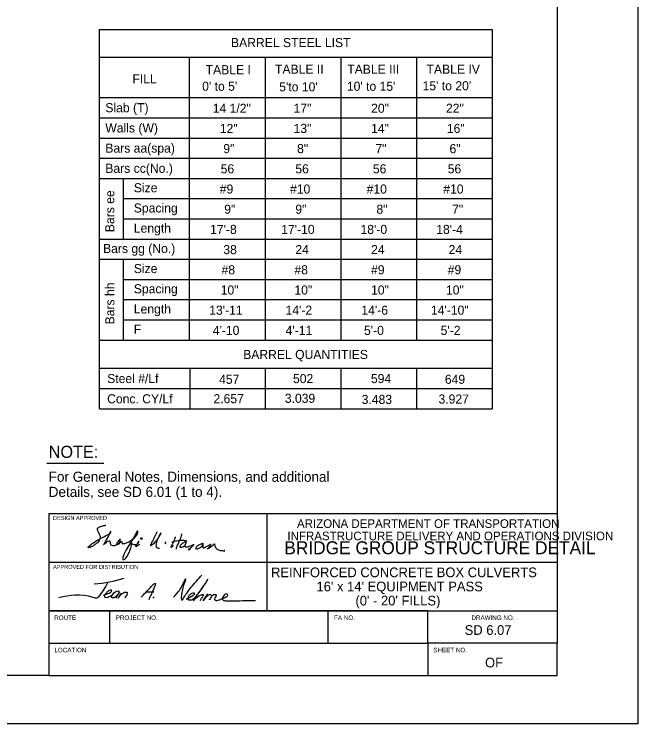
# Model space of a CAD drawing. Extents: x -0.08 to 2.83, y -0.03 to 1.92.
# Drawn here: x 2.029 to 2.833, y 0 to 0.915 of the extents above; entities that cross this region are included whole.
import ezdxf

# ---------------------------------------------------------------- set-up
doc = ezdxf.new("R2010")
doc.units = 0
for name, color, linetype in [('49', 7, 'Continuous'), ('55', 7, 'Continuous'), ('57', 7, 'Continuous'), ('62', 7, 'Continuous'), ('63', 7, 'Continuous')]:
    doc.layers.add(name, color=color, linetype=linetype)

msp = doc.modelspace()

# ---------------------------------------------------------------- linework, layer by layer
at = {"layer": '49'}
msp.add_line((2.13966, 0.49488), (2.13966, 0.49456), dxfattribs=at)
at = {"layer": '55'}
for p, q in [((2.13899, 0.89521), (2.13899, 0.40618)), ((2.13899, 0.89521), (2.64541, 0.89521)), ((2.64563, 0.89521), (2.64563, 0.40618)), ((2.13854, 0.85931), (2.64563, 0.85931)), ((2.2551, 0.85931), (2.2551, 0.49473)), ((2.35275, 0.85931), (2.35275, 0.49473)), ((2.45041, 0.85931), (2.45041, 0.49473)), ((2.54806, 0.85931), (2.54806, 0.49473)), ((2.13921, 0.80723), (2.64563, 0.80723)), ((2.13921, 0.78118), (2.64563, 0.78118)), ((2.13921, 0.75514), (2.64563, 0.75514)), ((2.13921, 0.7291), (2.64563, 0.7291)), ((2.13899, 0.70306), (2.64563, 0.70306)), ((2.17046, 0.62493), (2.17046, 0.70306)), ((2.17046, 0.67702), (2.64563, 0.67702)), ((2.17046, 0.65098), (2.64563, 0.65098)), ((2.13899, 0.62493), (2.64563, 0.62493)), ((2.13899, 0.59889), (2.64563, 0.59889)), ((2.17046, 0.49473), (2.17046, 0.59889)), ((2.17046, 0.57285), (2.64563, 0.57285)), ((2.17046, 0.54681), (2.64563, 0.54681)), ((2.17046, 0.52077), (2.64563, 0.52077)), ((2.13899, 0.49473), (2.64541, 0.49473)), ((2.13921, 0.45827), (2.64563, 0.45827)), ((2.25577, 0.45827), (2.25577, 0.40618)), ((2.35275, 0.45827), (2.35275, 0.40618)), ((2.45041, 0.45827), (2.45041, 0.40618)), ((2.54806, 0.45827), (2.54806, 0.40618)), ((2.13921, 0.43223), (2.64541, 0.43223)), ((2.13921, 0.40618), (2.64541, 0.40618))]:
    msp.add_line(p, q, dxfattribs=at)
at = {"layer": '57'}
for p, q in [((2.64631, 0.49473), (2.64631, 0.49456)), ((2.07131, 0.33607), (2.14477, 0.33607))]:
    msp.add_line(p, q, dxfattribs=at)
for points in [[(2.14765, 0.25562), (2.14682, 0.25571), (2.14575, 0.25542), (2.14487, 0.25532), (2.14397, 0.25503), (2.14311, 0.25475), (2.14203, 0.25429), (2.14043, 0.25389), (2.13901, 0.25331), (2.13813, 0.25284), (2.13758, 0.25263), (2.13706, 0.2524), (2.13655, 0.25191), (2.13637, 0.25143), (2.13634, 0.25038), (2.13646, 0.24988), (2.13669, 0.24909), (2.13707, 0.24825), (2.13754, 0.24729), (2.13802, 0.24626), (2.13848, 0.24568), (2.1391, 0.24444), (2.13948, 0.24359), (2.13985, 0.24285), (2.14011, 0.24143), (2.14019, 0.24048), (2.14006, 0.2395), (2.13967, 0.23801), (2.13887, 0.23634), (2.13823, 0.23519), (2.13663, 0.23333), (2.13514, 0.23225), (2.13328, 0.23066), (2.13172, 0.22974), (2.13035, 0.22879), (2.12878, 0.22803), (2.12732, 0.22727), (2.12575, 0.22684), (2.12502, 0.22692), (2.12462, 0.22757), (2.12482, 0.22803), (2.12536, 0.22854), (2.12583, 0.22911), (2.12687, 0.23003), (2.12901, 0.23148), (2.12993, 0.23223), (2.13153, 0.23337), (2.13326, 0.23448), (2.13516, 0.23574), (2.13681, 0.23665), (2.14133, 0.23946), (2.14564, 0.24158), (2.14763, 0.24265), (2.14977, 0.24371), (2.15138, 0.24446), (2.15266, 0.24523), (2.15357, 0.24588), (2.15395, 0.24653), (2.15403, 0.24774), (2.15357, 0.24792), (2.15339, 0.24772), (2.15326, 0.24744), (2.15189, 0.24408), (2.15104, 0.24225), (2.14793, 0.2371), (2.14615, 0.23392), (2.14537, 0.23259), (2.14456, 0.23092), (2.14471, 0.23073), (2.14621, 0.23237), (2.14786, 0.23379), (2.14933, 0.2349), (2.15041, 0.23553), (2.15025, 0.23554), (2.15166, 0.23596), (2.15233, 0.23575), (2.15248, 0.23551), (2.15292, 0.23413), (2.15298, 0.23275), (2.15347, 0.23157), (2.15416, 0.23064), (2.15662, 0.23007), (2.15903, 0.23008), (2.16063, 0.23083), (2.16326, 0.23175), (2.16493, 0.23298), (2.16588, 0.2341), (2.1662, 0.23616), (2.16645, 0.23743), (2.16619, 0.23773), (2.16568, 0.23744), (2.16444, 0.2361), (2.16299, 0.23465), (2.16243, 0.234), (2.16167, 0.23323), (2.16131, 0.23193), (2.16152, 0.23111), (2.16315, 0.23186), (2.16495, 0.23312), (2.16659, 0.23422), (2.1675, 0.23485)], [(2.1675, 0.23485), (2.16768, 0.23502), (2.16803, 0.23499), (2.16833, 0.23428), (2.16809, 0.23323), (2.1685, 0.23253), (2.16938, 0.23231), (2.17073, 0.23226), (2.17219, 0.23262), (2.17432, 0.23335), (2.17707, 0.2347), (2.17923, 0.23592), (2.18111, 0.23698), (2.18401, 0.23935), (2.18673, 0.24251), (2.1874, 0.24345), (2.18795, 0.24413), (2.18885, 0.24684), (2.18861, 0.24817), (2.18803, 0.24838), (2.18525, 0.24365), (2.18363, 0.24013), (2.17856, 0.23217), (2.17642, 0.22845), (2.17367, 0.22436), (2.17077, 0.21821), (2.16978, 0.21578), (2.16922, 0.21263), (2.16931, 0.21192), (2.17007, 0.21144), (2.17188, 0.21228), (2.17301, 0.21331), (2.17493, 0.21608), (2.17752, 0.22087), (2.17895, 0.22416), (2.17971, 0.22647), (2.18065, 0.22981), (2.18078, 0.23184), (2.18067, 0.23323), (2.18006, 0.23363), (2.17971, 0.23383), (2.17996, 0.23312), (2.18067, 0.23272), (2.18133, 0.23216), (2.18235, 0.23173), (2.18352, 0.2313), (2.18407, 0.23126), (2.18577, 0.23115), (2.18651, 0.23125), (2.18788, 0.23169), (2.18906, 0.23271), (2.18935, 0.23298), (2.19013, 0.23462), (2.19023, 0.23513), (2.18976, 0.23544), (2.18843, 0.23244), (2.1867, 0.2305), (2.18629, 0.22968), (2.18597, 0.22898), (2.18621, 0.22854), (2.18855, 0.23002), (2.18946, 0.2305), (2.19059, 0.23118), (2.19141, 0.23178)], [(2.21321, 0.24728), (2.21278, 0.24633), (2.21192, 0.2446), (2.21109, 0.24289), (2.20987, 0.24003), (2.20924, 0.23883), (2.20839, 0.23714), (2.20749, 0.23532), (2.20656, 0.23362), (2.20585, 0.23209), (2.20522, 0.23093), (2.20498, 0.23028), (2.20498, 0.22995), (2.20514, 0.22994), (2.20538, 0.22984), (2.20569, 0.22998), (2.20645, 0.23048), (2.20741, 0.23118), (2.20881, 0.23228), (2.21007, 0.23343), (2.2113, 0.23468), (2.21223, 0.23566), (2.21333, 0.23669), (2.21398, 0.23754), (2.2148, 0.23898), (2.21596, 0.24094), (2.21666, 0.24203), (2.21782, 0.24413), (2.21837, 0.24483), (2.21887, 0.24558), (2.21893, 0.24581), (2.21882, 0.24594), (2.21866, 0.246), (2.21854, 0.24593), (2.21806, 0.24521), (2.21715, 0.24405), (2.21599, 0.24204), (2.21572, 0.24131), (2.21528, 0.24042), (2.21488, 0.23963), (2.21393, 0.23749), (2.21329, 0.23598), (2.21302, 0.23478), (2.21269, 0.23374), (2.21253, 0.23244), (2.21229, 0.23068), (2.21218, 0.22945), (2.21231, 0.22828), (2.21257, 0.22781), (2.21318, 0.22732), (2.21379, 0.22691), (2.21433, 0.22667), (2.21497, 0.22648), (2.21556, 0.2264), (2.21619, 0.22636), (2.21665, 0.22637)], [(2.19468, 0.23875), (2.1943, 0.23878), (2.19381, 0.23888), (2.19338, 0.23913), (2.19307, 0.23928), (2.19284, 0.23933), (2.19253, 0.23933), (2.19238, 0.23916), (2.1922, 0.23895), (2.19217, 0.23886), (2.19224, 0.23861), (2.19245, 0.23854), (2.19273, 0.23851), (2.19302, 0.23849), (2.1935, 0.23855), (2.19382, 0.23856), (2.19419, 0.23856), (2.19455, 0.23867), (2.19471, 0.23872)], [(2.23711, 0.24121), (2.23674, 0.24001), (2.23642, 0.239), (2.23579, 0.23723), (2.23502, 0.23525), (2.23462, 0.2345), (2.23406, 0.23333), (2.23329, 0.23174), (2.23267, 0.23059), (2.23222, 0.22966), (2.23172, 0.22875), (2.2315, 0.22823), (2.23146, 0.2278), (2.23159, 0.22758), (2.23184, 0.22757), (2.232, 0.22763), (2.23258, 0.22801), (2.23313, 0.22838), (2.23337, 0.22858), (2.23364, 0.22878), (2.23378, 0.22887), (2.23399, 0.22905), (2.23421, 0.22928), (2.23441, 0.22947), (2.23448, 0.22961), (2.23467, 0.22983)], [(2.24473, 0.24483), (2.24497, 0.24428), (2.24498, 0.24372), (2.24493, 0.24321), (2.24468, 0.24225), (2.24431, 0.24076), (2.24388, 0.23971), (2.24318, 0.23801), (2.24267, 0.23695), (2.24213, 0.23588), (2.24099, 0.23343), (2.24057, 0.23259), (2.23951, 0.23037), (2.23933, 0.22998), (2.23898, 0.22908), (2.23857, 0.22768), (2.23835, 0.22672), (2.23821, 0.22563), (2.23811, 0.22523)], [(2.22443, 0.23244), (2.22472, 0.23308), (2.2246, 0.23376), (2.22436, 0.23406), (2.22408, 0.23412), (2.22398, 0.23393), (2.22388, 0.23324), (2.224, 0.23256), (2.22423, 0.23234), (2.22434, 0.2322), (2.22443, 0.23224), (2.2244, 0.23238)], [(2.23248, 0.23456), (2.23325, 0.23476), (2.2342, 0.23501), (2.23568, 0.23543), (2.23742, 0.23576), (2.23878, 0.23593), (2.24092, 0.23616), (2.24296, 0.23643), (2.24483, 0.23658), (2.24631, 0.23661), (2.24751, 0.23662), (2.24815, 0.23658), (2.24954, 0.23651), (2.25052, 0.23638), (2.25088, 0.23621), (2.25113, 0.23568), (2.2507, 0.2337), (2.25061, 0.23341), (2.25006, 0.23176), (2.24968, 0.23083), (2.24923, 0.2298), (2.24903, 0.22937), (2.24881, 0.22913), (2.24855, 0.22885), (2.24788, 0.22845), (2.24669, 0.22782), (2.24572, 0.22757), (2.24486, 0.22728), (2.24453, 0.22723), (2.24402, 0.22721), (2.24346, 0.22738), (2.24333, 0.22753), (2.24326, 0.22773), (2.24329, 0.22813), (2.24333, 0.22875), (2.24351, 0.22929), (2.24369, 0.22982), (2.24413, 0.23055), (2.24473, 0.23118), (2.24562, 0.23205), (2.24626, 0.23258), (2.24677, 0.23295), (2.24743, 0.23348), (2.24812, 0.23387), (2.24898, 0.23437), (2.24957, 0.23468), (2.25026, 0.23503), (2.25053, 0.23503), (2.25075, 0.23493), (2.25082, 0.23468), (2.25057, 0.23343), (2.25053, 0.23315), (2.25026, 0.23215), (2.24986, 0.23102), (2.2495, 0.23), (2.24939, 0.2295), (2.24935, 0.22926), (2.24932, 0.22911), (2.24933, 0.22867), (2.24944, 0.22839), (2.24977, 0.2281), (2.2499, 0.22803), (2.25012, 0.22803), (2.2505, 0.22796), (2.25113, 0.22796), (2.25153, 0.22798), (2.25188, 0.22807), (2.25251, 0.22818), (2.25313, 0.22828), (2.25369, 0.22836), (2.25436, 0.22853), (2.25515, 0.22883), (2.25633, 0.22935), (2.25781, 0.22992), (2.25893, 0.23036), (2.25968, 0.23067), (2.26019, 0.23098), (2.2608, 0.23112), (2.26094, 0.23098), (2.26057, 0.23036), (2.26004, 0.22976), (2.25931, 0.22903), (2.25887, 0.22862), (2.25828, 0.22803), (2.25718, 0.22698), (2.25408, 0.22424), (2.25384, 0.22398), (2.25413, 0.22412), (2.25504, 0.22455), (2.25579, 0.22489), (2.25632, 0.22513), (2.25663, 0.22528)], [(2.27233, 0.23026), (2.27212, 0.2318), (2.27153, 0.23226), (2.27104, 0.23214), (2.26923, 0.23137), (2.2681, 0.23077), (2.26717, 0.23022), (2.26638, 0.22968), (2.26546, 0.22897), (2.26466, 0.22842), (2.26423, 0.22782), (2.26369, 0.2272), (2.26337, 0.22659), (2.26336, 0.22625), (2.26337, 0.22586), (2.26366, 0.22562), (2.26398, 0.22548), (2.26441, 0.22542), (2.26464, 0.22542), (2.26516, 0.22547), (2.26554, 0.22556), (2.2664, 0.22583), (2.26779, 0.22633), (2.26861, 0.22685), (2.26952, 0.22746), (2.27029, 0.22808), (2.27109, 0.22873), (2.27183, 0.22942), (2.27243, 0.23006), (2.27312, 0.23148), (2.27319, 0.23218), (2.27303, 0.23268), (2.27271, 0.23234), (2.27258, 0.23171), (2.27262, 0.23101), (2.27263, 0.22988), (2.27258, 0.22914), (2.27257, 0.22827), (2.27259, 0.22769), (2.27259, 0.22686), (2.27266, 0.22673), (2.27281, 0.22671), (2.27373, 0.22695), (2.27465, 0.22718), (2.27539, 0.22753), (2.2761, 0.22788), (2.27641, 0.22803), (2.27723, 0.22842), (2.27798, 0.22885), (2.27917, 0.22956), (2.28043, 0.2302), (2.28166, 0.23094), (2.28213, 0.23122), (2.28297, 0.23177), (2.28313, 0.23174), (2.28293, 0.23104), (2.28261, 0.23033), (2.28215, 0.22959), (2.28155, 0.22873), (2.28111, 0.22811), (2.27994, 0.22684), (2.27862, 0.22555), (2.27853, 0.22532), (2.27868, 0.22528), (2.28006, 0.22628), (2.28188, 0.22757), (2.28343, 0.22858), (2.28454, 0.22938), (2.28567, 0.23033), (2.28698, 0.23175), (2.28705, 0.23179), (2.28728, 0.23206), (2.28742, 0.23198), (2.28766, 0.23069), (2.2879, 0.22988), (2.28822, 0.22903), (2.28848, 0.22836), (2.28878, 0.22766), (2.28907, 0.22713), (2.28958, 0.22627), (2.28999, 0.22582), (2.29046, 0.22545), (2.29094, 0.22511), (2.29132, 0.22488), (2.29228, 0.2244), (2.29317, 0.22411), (2.29438, 0.22369), (2.29511, 0.22358), (2.29611, 0.22335), (2.29699, 0.22325), (2.29795, 0.22323), (2.29877, 0.22316), (2.29951, 0.22312), (2.30051, 0.22297), (2.30093, 0.22293), (2.30071, 0.22307), (2.30038, 0.22326), (2.30007, 0.22348), (2.29987, 0.2236)]]:
    msp.add_lwpolyline(points, dxfattribs=at)
msp.add_arc((2.12576, 0.32651), 0.14607, 272.67102, 288.18495, dxfattribs=at)
msp.add_ellipse((2.1597, 0.16674), major_axis=(0.00445, 0.00414), ratio=0.425517, dxfattribs=at)
for points in [[(2.23468, 0.16329), (2.24247, 0.17206), (2.2468, 0.17993), (2.25055, 0.18688), (2.24978, 0.18448), (2.24873, 0.18168), (2.24786, 0.17853), (2.24593, 0.17117), (2.24575, 0.15925), (2.24768, 0.16223), (2.25383, 0.17108), (2.25913, 0.17799), (2.26284, 0.18217), (2.26953, 0.18973), (2.27125, 0.19154)], [(2.27913, 0.18645), (2.26691, 0.16866), (2.26002, 0.15884), (2.27102, 0.16638), (2.27174, 0.16649), (2.27323, 0.16633), (2.27308, 0.16531), (2.27148, 0.1627), (2.26896, 0.15855)], [(2.15026, 0.18245), (2.13747, 0.1632), (2.13658, 0.16231), (2.13123, 0.16275), (2.08684, 0.16261)], [(2.19315, 0.16345), (2.19896, 0.16933), (2.20501, 0.17574), (2.20724, 0.17819), (2.20941, 0.1803), (2.21138, 0.18096), (2.2113, 0.17937), (2.21077, 0.17794), (2.20906, 0.17363), (2.20497, 0.16464), (2.20276, 0.16)], [(2.25098, 0.16082), (2.25957, 0.16531), (2.26102, 0.16633), (2.26204, 0.16779), (2.26175, 0.16822), (2.26001, 0.16837), (2.25666, 0.16706), (2.25405, 0.16415), (2.25332, 0.16197), (2.25332, 0.16095), (2.25581, 0.15961), (2.26008, 0.16091), (2.26408, 0.1646), (2.27308, 0.1773)], [(2.14468, 0.16595), (2.15189, 0.16856), (2.15402, 0.16987), (2.155, 0.1715), (2.155, 0.17216), (2.15369, 0.17232), (2.15108, 0.1715), (2.1483, 0.16889), (2.1465, 0.16676), (2.14569, 0.16464), (2.14634, 0.16333), (2.14912, 0.16317), (2.15298, 0.16457), (2.15512, 0.16583), (2.15712, 0.16742), (2.15716, 0.16742)], [(2.16416, 0.17088), (2.16467, 0.1696), (2.16316, 0.16671), (2.16115, 0.16432), (2.16077, 0.16281), (2.16153, 0.16206)], [(2.16731, 0.16847), (2.16582, 0.16612), (2.16341, 0.16218), (2.16591, 0.16562), (2.16907, 0.16797), (2.17045, 0.16897), (2.17488, 0.16916), (2.17524, 0.16783), (2.17478, 0.16626), (2.17294, 0.16391), (2.17196, 0.1618)], [(2.20019, 0.17022), (2.20269, 0.17029), (2.20533, 0.17015), (2.20922, 0.17029)], [(2.27878, 0.16743), (2.27342, 0.15912), (2.27381, 0.15951), (2.27965, 0.16591), (2.28139, 0.16656), (2.28339, 0.16597), (2.28369, 0.16421), (2.28271, 0.16235), (2.28114, 0.1599), (2.28349, 0.16333), (2.28546, 0.166), (2.28955, 0.16646), (2.28936, 0.16401), (2.28761, 0.1603), (2.28796, 0.15989), (2.28878, 0.1592), (2.29346, 0.1599), (2.29972, 0.16196), (2.30275, 0.16362), (2.30493, 0.16569), (2.30353, 0.16734), (2.30001, 0.16587), (2.29825, 0.16323), (2.29786, 0.16235), (2.29776, 0.16049), (2.30158, 0.15863), (2.30871, 0.15844), (2.34054, 0.15879)], [(2.20987, 0.16382), (2.20906, 0.16268), (2.20808, 0.16202)]]:
    msp.add_spline(points, degree=3, dxfattribs=at)
at = {"layer": '63'}
for p, q in [((2.83333, 1.83333), (2.83333, 0)), ((2.72918, 0.27077), (2.07387, 0.27077)), ((2.07387, 0.27077), (2.07387, 0.06244)), ((2.35493, 0.27077), (2.35493, 0.14578)), ((2.57284, 0.27077), (2.57284, 0.27077)), ((2.07387, 0.20828), (2.72918, 0.20828)), ((2.07387, 0.20647), (2.07387, 0.20647)), ((2.07387, 0.20647), (2.07387, 0.20647)), ((2.07387, 0.14578), (2.72918, 0.14578)), ((2.07387, 0.14397), (2.07387, 0.14397)), ((2.08908, 0.14583), (2.08931, 0.14583)), ((2.15266, 0.10411), (2.15266, 0.14578)), ((2.23742, 0.14583), (2.23742, 0.14583)), ((2.23742, 0.14583), (2.23742, 0.14583)), ((2.23742, 0.14583), (2.23742, 0.14583)), ((2.23742, 0.14583), (2.23742, 0.14583)), ((2.43435, 0.10411), (2.43435, 0.14578)), ((2.07387, 0.10411), (2.56251, 0.10411)), ((2.56251, 0.10411), (2.56251, 0.06244)), ((2.72918, 0.06244), (2.72918, 0.10411)), ((2.07387, 0.06244), (2.72918, 0.06244)), ((2.83333, 0), (0, 0)), ((2.83, 0.00033), (2.83, 0.00033))]:
    msp.add_line(p, q, dxfattribs=at)
msp.add_lwpolyline([(0.16668, 0.06244), (0.16668, 1.77077), (2.72918, 1.77077), (2.72918, 0.10411), (2.56251, 0.10411), (2.56251, 0.14578), (2.07387, 0.14578), (2.07387, 0.06244)], close=True, dxfattribs=at)

# ---------------------------------------------------------------- texts
at = {"layer": '55'}
for s, p in [('DESIGN APPROVED', (2.07944, 0.26274)), ('APPROVED FOR DISTRIBUTION', (2.07944, 0.19966))]:
    msp.add_text(s, height=0.0052084, dxfattribs=at).set_placement(p)
at = {"layer": '57'}
for s, height, p in [('BARREL STEEL LIST', 0.0117167, (2.30885, 0.87235)), ('TABLE I', 0.011717, (2.27624, 0.83739)), ('TABLE II', 0.011717, (2.36563, 0.83798)), ('TABLE III', 0.011717, (2.45873, 0.83798)), ('TABLE IV', 0.011717, (2.56095, 0.83798)), ('FILL', 0.011717, (2.18185, 0.82551)), ("0' to 5'", 0.011717, (2.27168, 0.8161)), ("5'to 10'", 0.011717, (2.37106, 0.81532)), ("10' to 15'", 0.011717, (2.45825, 0.81602)), ("15' to 20'", 0.011717, (2.55591, 0.81669)), ('Slab (T)', 0.011717, (2.14686, 0.78839)), ('14 1/2"', 0.011717, (2.28535, 0.78769)), ('17"', 0.011717, (2.38955, 0.78771)), ('20"', 0.011717, (2.4895, 0.78771)), ('22"', 0.011717, (2.58601, 0.78771)), ('Walls (W)', 0.011717, (2.14686, 0.76236)), ('12"', 0.011717, (2.29446, 0.76166)), ('13"', 0.011717, (2.38955, 0.76168)), ('14"', 0.011717, (2.4895, 0.76168)), ('16"', 0.011717, (2.58716, 0.76168)), ('Bars aa(spa)', 0.0117167, (2.14686, 0.73633)), ('9"', 0.011717, (2.29897, 0.73563)), ('8"', 0.011717, (2.39407, 0.73564)), ('7"', 0.011717, (2.4951, 0.73564)), ('6"', 0.011717, (2.59057, 0.73564)), ('Bars cc(No.)', 0.0117167, (2.14686, 0.71029)), ('56', 0.011717, (2.29556, 0.70959)), ('56', 0.011717, (2.39181, 0.70961)), ('56', 0.011717, (2.49177, 0.70961)), ('56', 0.011717, (2.58828, 0.70961)), ('Size', 0.011717, (2.18358, 0.68517)), ('#9', 0.011717, (2.29439, 0.68356)), ('#10', 0.011717, (2.38499, 0.68358)), ('#10', 0.011717, (2.48378, 0.68358)), ('#10', 0.011717, (2.58258, 0.68358)), ('Spacing', 0.011717, (2.18358, 0.65913)), ('9"', 0.011717, (2.30015, 0.65753)), ('9"', 0.011717, (2.39181, 0.65754)), ('8"', 0.011717, (2.49636, 0.65754)), ('7"', 0.011717, (2.59394, 0.65754)), ('Length', 0.011717, (2.18358, 0.6331)), ("17'-8", 0.011717, (2.28191, 0.63149)), ("17'-10", 0.011717, (2.3736, 0.63151)), ("18'-0", 0.011717, (2.47581, 0.63151)), ("18'-4", 0.011717, (2.57346, 0.63151)), ('Bars gg (No.)', 0.0117, (2.14397, 0.6069)), ('38', 0.011717, (2.29901, 0.60546)), ('24', 0.011717, (2.39181, 0.60548)), ('24', 0.011717, (2.48947, 0.60548)), ('24', 0.011717, (2.58942, 0.60548)), ('Size', 0.011717, (2.18358, 0.58103)), ('#8', 0.011717, (2.29671, 0.57943)), ('#8', 0.011717, (2.39066, 0.57944)), ('#9', 0.011717, (2.48946, 0.57944)), ('#9', 0.011717, (2.58827, 0.57944)), ('Spacing', 0.011717, (2.18358, 0.555)), ('10"', 0.011717, (2.29563, 0.55339)), ('10"', 0.011717, (2.39067, 0.55341)), ('10"', 0.011717, (2.48947, 0.55341)), ('10"', 0.011717, (2.58598, 0.55341)), ('Length', 0.011717, (2.18358, 0.52897)), ("13'-11", 0.011717, (2.28079, 0.52736)), ("14'-2", 0.011717, (2.37919, 0.52738)), ("14'-6", 0.011717, (2.47694, 0.52738)), ('14\'-10"', 0.011717, (2.56662, 0.52738)), ('F', 0.01172, (2.18358, 0.50293)), ("4'-10", 0.011717, (2.28538, 0.50133)), ("4'-11", 0.011717, (2.37929, 0.50134)), ("5'-0", 0.011717, (2.48036, 0.50134)), ("5'-2", 0.011717, (2.57917, 0.50134)), ('BARREL QUANTITIES', 0.0117, (2.3246, 0.47029)), ('Steel #/Lf', 0.0117, (2.14926, 0.43927)), ('457', 0.0117, (2.29352, 0.43828)), ('502', 0.0117, (2.38881, 0.43923)), ('594', 0.0117, (2.48929, 0.43923)), ('649', 0.0117, (2.58458, 0.43829)), ('Conc. CY/Lf', 0.0117, (2.14921, 0.41314)), ('2.657', 0.0117, (2.28631, 0.41328)), ('3.039', 0.0117, (2.3783, 0.41376)), ('3.483', 0.0117, (2.47736, 0.41235)), ('3.927', 0.0117, (2.57642, 0.41282)), ('NOTE:', 0.015625, (2.07387, 0.34278)), ('For General Notes, Dimensions, and additional', 0.0130208, (2.07387, 0.31201)), ('Details, see SD 6.01 (1 to 4).', 0.0130208, (2.07387, 0.29248))]:
    msp.add_text(s, height=height, dxfattribs=at).set_placement(p)
for s, p in [('Bars ee', (2.15843, 0.6338)), ('Bars hh', (2.15851, 0.51488))]:
    msp.add_text(s, height=0.011717, rotation=90, dxfattribs=at).set_placement(p)
at = {"layer": '62'}
for s, p in [('REINFORCED CONCRETE BOX CULVERTS', (2.3605, 0.189)), ("16' x 14' EQUIPMENT PASS", (2.4191, 0.17078)), ("(0' - 20' FILLS)", (2.46933, 0.15255)), ('SD 6.07', (2.61011, 0.11464))]:
    msp.add_text(s, height=0.0125, dxfattribs=at).set_placement(p)
at = {"layer": '63'}
for s, height, p in [('ARIZONA DEPARTMENT OF TRANSPORTATION', 0.0111083, (2.39394, 0.25258)), ('INFRASTRUCTURE DELIVERY AND OPERATIONS DIVISION', 0.0111083, (2.38162, 0.23663)), ('BRIDGE GROUP STRUCTURE DETAIL', 0.0166667, (2.37762, 0.2186)), ('ROUTE', 0.005833, (2.08105, 0.13383)), ('PROJECT NO.', 0.0058333, (2.16034, 0.13383)), ('FA NO.', 0.005833, (2.44175, 0.13383)), ('DRAWING NO.', 0.0058334, (2.61888, 0.13383)), ('LOCATION', 0.005833, (2.08128, 0.09217)), ('SHEET NO.', 0.005833, (2.56964, 0.09217)), ('OF', 0.0125, (2.63638, 0.0727))]:
    msp.add_text(s, height=height, dxfattribs=at).set_placement(p)

doc.saveas('drawing.dxf')
